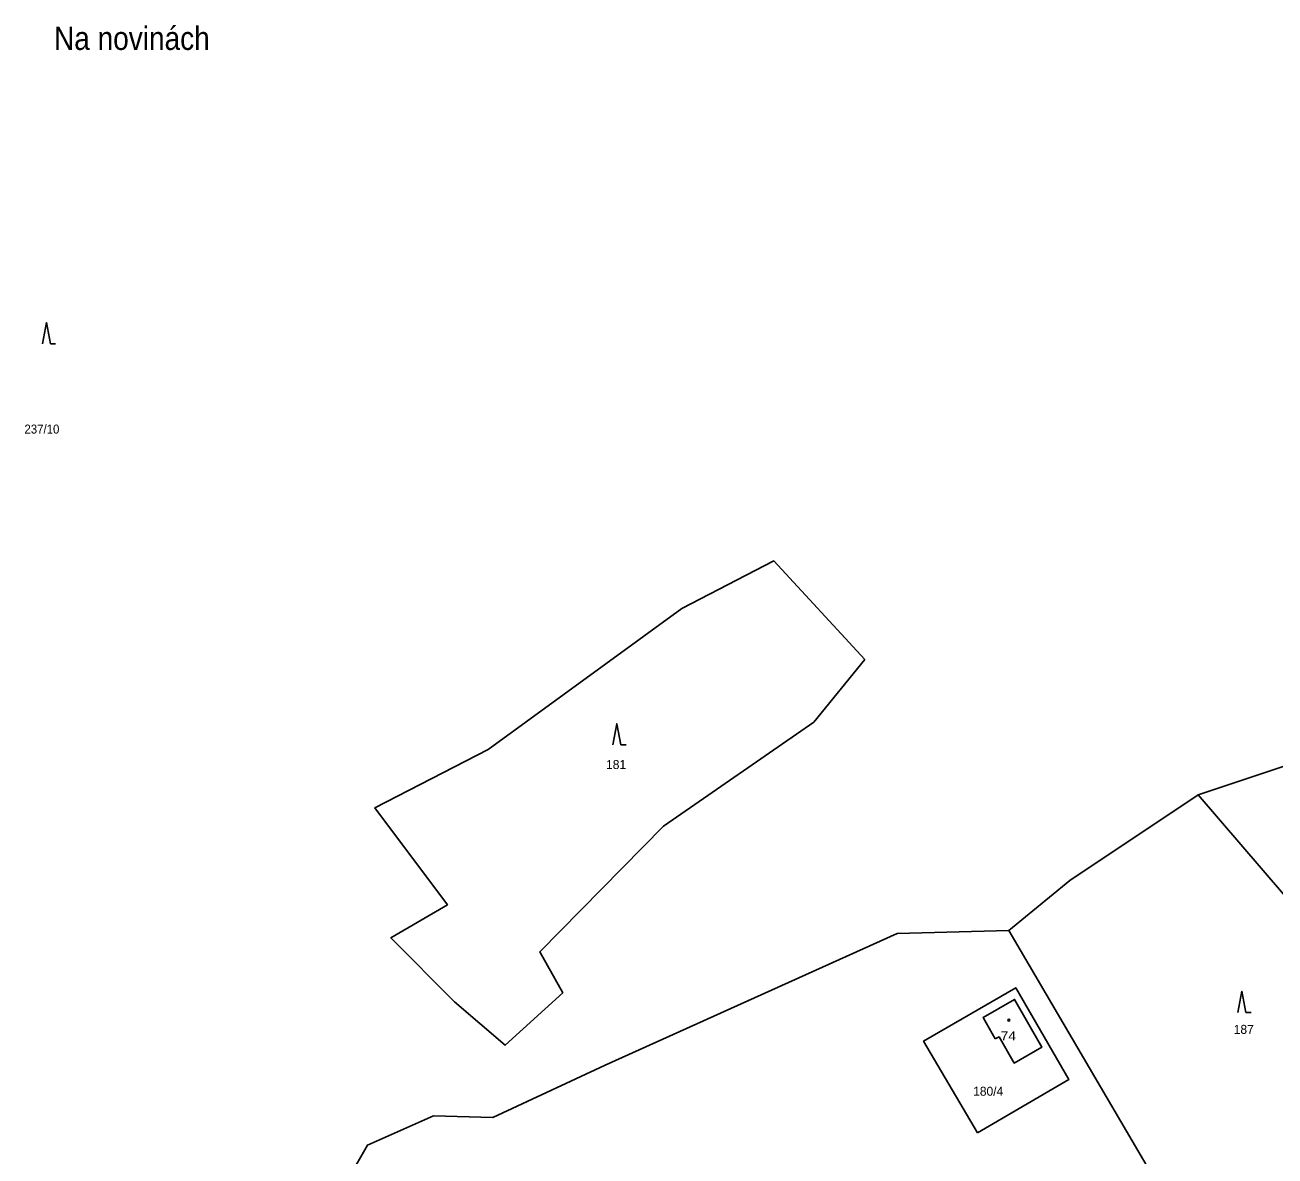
# Model space of a CAD drawing. Extents: x -632162 to -629607, y -1101195 to -1098670.
# Drawn here: x -631277.1 to -631040.8, y -1099541.5 to -1099327.9 of the extents above; entities that cross this region are included whole.
import ezdxf
from ezdxf.enums import TextEntityAlignment as Align

# ---------------------------------------------------------------- set-up
doc = ezdxf.new("R2010")
doc.units = 0
doc.header["$LTSCALE"] = 0.68
for name, color, linetype, lineweight in [('1', 7, 'Continuous', 25), ('3', 7, 'Continuous', 25), ('5', 7, 'Continuous', 25), ('7', 7, 'Continuous', 13)]:
    doc.layers.add(name, color=color, linetype=linetype, lineweight=lineweight)
doc.layers.add('2', color=7, linetype='Continuous')

msp = doc.modelspace()

# ---------------------------------------------------------------- linework, layer by layer
at = {"layer": '1'}
for points in [[(-631118.37, -1099447.73), (-631135.57, -1099429.11), (-631152.98, -1099438.12), (-631189.59, -1099464.7), (-631211, -1099475.78), (-631197.25, -1099494.07), (-631207.95, -1099500.28), (-631195.91, -1099512.42), (-631186.35, -1099520.6), (-631175.46, -1099510.71), (-631179.81, -1099502.96), (-631156.44, -1099479.19), (-631128.03, -1099459.56)], [(-631097.04, -1099537.12), (-631107.25, -1099519.8), (-631089.84, -1099509.73), (-631079.77, -1099527.05)], [(-631093.73, -1099519.37), (-631092.97, -1099519.03), (-631090.11, -1099523.98), (-631084.92, -1099520.99), (-631090.04, -1099511.94), (-631096.01, -1099515.38)]]:
    msp.add_lwpolyline(points, close=True, dxfattribs=at)
for points in [[(-630939.7, -1099485.24), (-630960.44, -1099472.59), (-630988.58, -1099451.03), (-631055.38, -1099473.27)], [(-631055.38, -1099473.27), (-631079.62, -1099489.48), (-631091.14, -1099498.92)], [(-631006.36, -1099537.27), (-631006.59, -1099530.01), (-631055.38, -1099473.27)], [(-631091.14, -1099498.92), (-631112.27, -1099499.47), (-631167.47, -1099524.35), (-631188.7, -1099534.26), (-631199.88, -1099533.92), (-631212.38, -1099539.47), (-631219.33, -1099551.54)], [(-631006.36, -1099537.27), (-631021.08, -1099546.27), (-631059.67, -1099552.5), (-631091.14, -1099498.92)]]:
    msp.add_lwpolyline(points, dxfattribs=at)
at = {"layer": '3'}
for p, q in [((-631272.32, -1099388.07), (-631271.324, -1099388.07)), ((-631164.5, -1099463.87), (-631163.504, -1099463.87)), ((-631046.33, -1099514.39), (-631045.334, -1099514.39))]:
    msp.add_line(p, q, dxfattribs=at)
for points in [[(-631272.32, -1099388.07), (-631273.07, -1099384.07), (-631273.82, -1099388.07)], [(-631164.5, -1099463.87), (-631165.25, -1099459.87), (-631166, -1099463.87)], [(-631046.33, -1099514.39), (-631047.08, -1099510.39), (-631047.83, -1099514.39)]]:
    msp.add_lwpolyline(points, dxfattribs=at)
at = {"layer": '5'}
msp.add_circle((-631091.1368, -1099515.8792), 0.175, dxfattribs=at)

# ---------------------------------------------------------------- texts
at = {"layer": '2'}
for s, width, p in [('237/10', 0.95, (-631273.919, -1099405.05)), ('74', 1.15, (-631091.25, -1099519.7))]:
    msp.add_text(s, height=1.7, dxfattribs=dict(at, width=width)).set_placement(p, align=Align.CENTER)
for s, p in [('181', (-631165.379, -1099468.42)), ('187', (-631046.729, -1099518.45)), ('180/4', (-631095.04, -1099530.14))]:
    msp.add_text(s, height=1.7, dxfattribs=at).set_placement(p, align=Align.CENTER)
at = {"layer": '7', "width": 0.9}
msp.add_text('Na novinách', height=4.4, dxfattribs=at).set_placement((-631256.91, -1099332.578), align=Align.CENTER)

doc.saveas('drawing.dxf')
